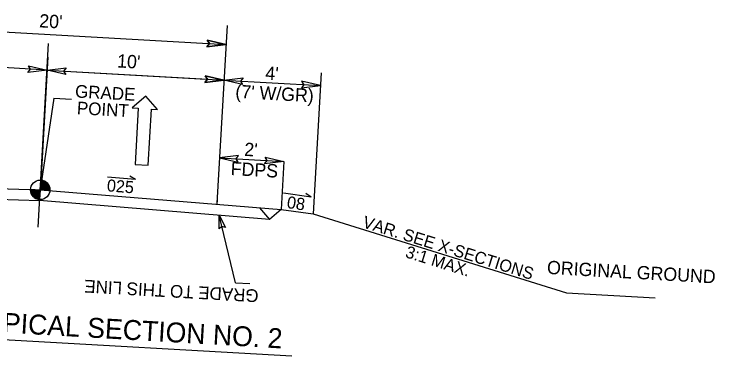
# Model space of a CAD drawing. Extents: x 2604316 to 2606605, y 617090 to 619543.
# Drawn here: x 2606244.6 to 2606592.8, y 617090 to 617260 of the extents above; entities that cross this region are included whole.
import ezdxf

# ---------------------------------------------------------------- set-up
doc = ezdxf.new("R2010")
doc.units = 0
for name, color, linetype in [('Pattern 1', 7, 'Continuous'), ('Prop Vertical Profile Curve Label', 7, 'Continuous'), ('Typical Grade Point Symbol CELL', 7, 'Continuous'), ('Typical Pavement Slope CELL', 7, 'Continuous'), ('Typical Pavement Slope Information CELL', 7, 'Continuous'), ('Typical Terminator CELL', 7, 'Continuous'), ('Typical Text Centerline CELL', 7, 'Continuous'), ('Typical Text General CELL', 7, 'Continuous')]:
    doc.layers.add(name, color=color, linetype=linetype)

msp = doc.modelspace()

# ---------------------------------------------------------------- linework, layer by layer
at = {"layer": 'Pattern 1'}
msp.add_line((2606519.08, 617121.38), (2606563.01, 617118.87), dxfattribs=at)
at = {"layer": 'Prop Vertical Profile Curve Label'}
for p, q in [((2606137.6, 617176.44), (2606257.57, 617172.61)), ((2606257.57, 617172.61), (2606377.21, 617162.79)), ((2606142.72, 617170.92), (2606257.27, 617167.27)), ((2606371.49, 617157.89), (2606257.27, 617167.27)), ((2606366.55, 617163.67), (2606371.49, 617157.89)), ((2606377.21, 617162.79), (2606371.49, 617157.89)), ((2606377.21, 617162.79), (2606393.11, 617160.6)), ((2606354.5, 617126.47), (2606346.51, 617159.95)), ((2606393.11, 617160.6), (2606519.08, 617121.38)), ((2606354.5, 617126.47), (2606361.62, 617126.07))]:
    msp.add_line(p, q, dxfattribs=at)
at = {"layer": 'Typical Grade Point Symbol CELL'}
for p, q in [((2606257.57, 617172.61), (2606257.85, 617177.44)), ((2606252.75, 617172.88), (2606257.57, 617172.61)), ((2606257.29, 617167.78), (2606257.57, 617172.61)), ((2606257.57, 617172.61), (2606257.29, 617167.78)), ((2606262.4, 617172.33), (2606257.57, 617172.61))]:
    msp.add_line(p, q, dxfattribs=at)
for points in [[(2606257.89, 617177.43), (2606257.89, 617177.43), (2606257.61, 617172.61)], [(2606257.99, 617177.43), (2606257.71, 617172.6)], [(2606258.08, 617177.41), (2606257.81, 617172.6)], [(2606258.18, 617177.41), (2606257.9, 617172.59)], [(2606258.27, 617177.39), (2606258, 617172.59)], [(2606258.37, 617177.37), (2606258.1, 617172.58)], [(2606258.47, 617177.36), (2606258.19, 617172.57)], [(2606258.56, 617177.34), (2606258.29, 617172.57)], [(2606258.66, 617177.33), (2606258.39, 617172.56)], [(2606258.75, 617177.3), (2606258.48, 617172.56)], [(2606258.85, 617177.27), (2606258.58, 617172.55)], [(2606258.94, 617177.24), (2606258.68, 617172.55)], [(2606259.04, 617177.22), (2606258.77, 617172.54)], [(2606259.13, 617177.18), (2606258.87, 617172.54)], [(2606259.23, 617177.15), (2606258.97, 617172.53)], [(2606259.32, 617177.11), (2606259.06, 617172.52)], [(2606259.42, 617177.08), (2606259.16, 617172.52)], [(2606259.51, 617177.04), (2606259.26, 617172.51)], [(2606259.61, 617176.99), (2606259.35, 617172.51)], [(2606259.7, 617176.94), (2606259.45, 617172.5)], [(2606259.8, 617176.89), (2606259.55, 617172.5)], [(2606259.89, 617176.85), (2606259.64, 617172.49)], [(2606259.98, 617176.8), (2606259.74, 617172.49)], [(2606260.08, 617176.74), (2606259.83, 617172.48)], [(2606260.17, 617176.68), (2606259.93, 617172.48)], [(2606260.26, 617176.62), (2606260.03, 617172.47)], [(2606260.36, 617176.56), (2606260.12, 617172.46)], [(2606260.45, 617176.49), (2606260.22, 617172.46)], [(2606260.54, 617176.42), (2606260.32, 617172.45)], [(2606260.64, 617176.34), (2606260.41, 617172.45)], [(2606260.73, 617176.27), (2606260.51, 617172.44)], [(2606260.82, 617176.19), (2606260.61, 617172.44)], [(2606260.91, 617176.1), (2606260.7, 617172.43)], [(2606261, 617176.01), (2606260.8, 617172.43)], [(2606261.1, 617175.92), (2606260.9, 617172.42)], [(2606252.77, 617172.88), (2606252.74, 617172.36)], [(2606252.86, 617172.88), (2606252.8, 617171.78)], [(2606252.96, 617172.87), (2606252.88, 617171.44)], [(2606253.06, 617172.87), (2606252.96, 617171.14)], [(2606253.15, 617172.86), (2606253.04, 617170.91)], [(2606253.25, 617172.86), (2606253.13, 617170.7)], [(2606253.35, 617172.85), (2606253.21, 617170.51)], [(2606253.44, 617172.84), (2606253.3, 617170.34)], [(2606253.54, 617172.84), (2606253.39, 617170.18)], [(2606253.64, 617172.83), (2606253.48, 617170.03)], [(2606253.73, 617172.83), (2606253.57, 617169.9)], [(2606253.83, 617172.82), (2606253.66, 617169.78)], [(2606253.93, 617172.82), (2606253.75, 617169.65)], [(2606254.02, 617172.81), (2606253.84, 617169.54)], [(2606254.12, 617172.81), (2606253.93, 617169.43)], [(2606254.21, 617172.8), (2606254.02, 617169.33)], [(2606254.31, 617172.8), (2606254.11, 617169.23)], [(2606254.41, 617172.79), (2606254.2, 617169.14)], [(2606254.5, 617172.78), (2606254.29, 617169.05)], [(2606254.6, 617172.78), (2606254.38, 617168.97)], [(2606254.7, 617172.77), (2606254.48, 617168.89)], [(2606254.79, 617172.77), (2606254.57, 617168.82)], [(2606254.89, 617172.76), (2606254.66, 617168.75)], [(2606254.99, 617172.76), (2606254.75, 617168.68)], [(2606255.08, 617172.75), (2606254.85, 617168.61)], [(2606255.18, 617172.75), (2606254.94, 617168.55)], [(2606255.28, 617172.74), (2606255.03, 617168.49)], [(2606255.37, 617172.73), (2606255.13, 617168.43)], [(2606255.47, 617172.73), (2606255.22, 617168.39)], [(2606255.57, 617172.72), (2606255.32, 617168.34)], [(2606255.66, 617172.72), (2606255.41, 617168.29)], [(2606255.76, 617172.71), (2606255.5, 617168.24)], [(2606255.86, 617172.71), (2606255.6, 617168.19)], [(2606255.95, 617172.7), (2606255.69, 617168.15)], [(2606256.05, 617172.7), (2606255.79, 617168.12)], [(2606256.15, 617172.69), (2606255.88, 617168.08)], [(2606256.24, 617172.69), (2606255.98, 617168.05)], [(2606256.34, 617172.68), (2606256.07, 617168.01)], [(2606256.44, 617172.67), (2606256.17, 617167.99)], [(2606256.53, 617172.67), (2606256.26, 617167.96)], [(2606256.63, 617172.66), (2606256.36, 617167.93)], [(2606256.72, 617172.66), (2606256.45, 617167.91)], [(2606256.82, 617172.65), (2606256.55, 617167.89)], [(2606256.92, 617172.65), (2606256.65, 617167.86)], [(2606257.01, 617172.64), (2606256.74, 617167.85)], [(2606257.11, 617172.64), (2606256.84, 617167.83)], [(2606257.21, 617172.63), (2606256.93, 617167.81)], [(2606257.3, 617172.62), (2606257.03, 617167.81)], [(2606257.4, 617172.62), (2606257.13, 617167.79)], [(2606257.5, 617172.61), (2606257.22, 617167.79), (2606257.22, 617167.79)], [(2606261.19, 617175.81), (2606260.99, 617172.41)], [(2606261.28, 617175.71), (2606261.09, 617172.41)], [(2606261.37, 617175.6), (2606261.19, 617172.4)], [(2606261.46, 617175.48), (2606261.28, 617172.4)], [(2606261.55, 617175.35), (2606261.38, 617172.39)], [(2606261.64, 617175.22), (2606261.48, 617172.39)], [(2606261.73, 617175.07), (2606261.57, 617172.38)], [(2606261.81, 617174.92), (2606261.67, 617172.38)], [(2606261.9, 617174.75), (2606261.76, 617172.37)], [(2606261.99, 617174.57), (2606261.86, 617172.37)], [(2606262.07, 617174.37), (2606261.96, 617172.36)], [(2606262.16, 617174.13), (2606262.05, 617172.35)], [(2606262.24, 617173.86), (2606262.15, 617172.35)], [(2606262.31, 617173.52), (2606262.25, 617172.34)], [(2606262.38, 617173.02), (2606262.34, 617172.34)]]:
    msp.add_lwpolyline(points, dxfattribs=at)
msp.add_circle((2606257.57, 617172.61), 4.83, dxfattribs=at)
for start, end in [(356.7307, 86.7307), (176.7307, 266.7307)]:
    msp.add_arc((2606257.57, 617172.61), 4.83, start, end, dxfattribs=at)
at = {"layer": 'Typical Pavement Slope CELL'}
for p, q in [((2606174.11, 617254.77), (2606349.82, 617244.76)), ((2606350.36, 617254.19), (2606345.34, 617166.01)), ((2606350.36, 617254.19), (2606345.34, 617166.01)), ((2606260.96, 617232.1), (2606173.1, 617237.1)), ((2606261.32, 617238.49), (2606257.64, 617173.76)), ((2606260.96, 617232.1), (2606340.83, 617227.55)), ((2606260.96, 617232.1), (2606348.82, 617227.09)), ((2606397.1, 617230.75), (2606393.11, 617160.6)), ((2606348.82, 617227.09), (2606396.74, 617224.36)), ((2606264.33, 617218.14), (2606257.57, 617172.61)), ((2606264.33, 617218.14), (2606273.12, 617217.64)), ((2606310, 617219.21), (2606303.25, 617213.28)), ((2606315.83, 617212.57), (2606310, 617219.21)), ((2606303.25, 617213.28), (2606306.25, 617213.11)), ((2606306.25, 617213.11), (2606304.66, 617185.16)), ((2606311.25, 617184.78), (2606312.84, 617212.74)), ((2606312.84, 617212.74), (2606315.83, 617212.57)), ((2606346.62, 617188.53), (2606378.57, 617186.71)), ((2606378.57, 617186.71), (2606377.21, 617162.79)), ((2606304.66, 617185.16), (2606311.25, 617184.78)), ((2606302.16, 617179.56), (2606304.95, 617177.98)), ((2606290.99, 617179.06), (2606304.95, 617177.98)), ((2606378.37, 617171.04), (2606392.24, 617169.13)), ((2606389.55, 617170.87), (2606392.24, 617169.13)), ((2606345.43, 617167.61), (2606345.3, 617165.41)), ((2606142.71, 617103.71), (2606382.64, 617090.04))]:
    msp.add_line(p, q, dxfattribs=at)
at = {"layer": 'Typical Terminator CELL'}
for points in [[(2606340.56, 617246.91), (2606349.82, 617244.76), (2606340.32, 617243.64), (2606341.61, 617245.23)], [(2606340.37, 617243.68), (2606349.82, 617244.76), (2606340.51, 617246.96), (2606341.61, 617245.23)], [(2606251.69, 617234.24), (2606260.96, 617232.1), (2606251.45, 617230.97), (2606252.75, 617232.56)], [(2606270.23, 617229.95), (2606260.96, 617232.1), (2606270.46, 617233.22), (2606269.17, 617231.63)], [(2606339.55, 617229.24), (2606348.82, 617227.09), (2606339.31, 617225.96), (2606340.6, 617227.56)], [(2606339.37, 617226.01), (2606348.82, 617227.09), (2606339.5, 617229.29), (2606340.6, 617227.56)], [(2606358.08, 617224.95), (2606348.82, 617227.09), (2606358.32, 617228.22), (2606357.03, 617226.62)], [(2606387.29, 617223.28), (2606396.74, 617224.36), (2606387.42, 617226.56), (2606388.53, 617224.83)], [(2606356.07, 617189.61), (2606346.62, 617188.53), (2606355.94, 617186.33), (2606354.84, 617188.06)], [(2606369.3, 617188.86), (2606378.57, 617186.71), (2606369.06, 617185.58), (2606370.35, 617187.18)], [(2606346.46, 617153.19), (2606346.51, 617159.95), (2606349.67, 617153.92), (2606347.85, 617154.35)]]:
    msp.add_lwpolyline(points, close=True, dxfattribs=at)
at = {"layer": 'Typical Text Centerline CELL'}
msp.add_line((2606256.52, 617154.06), (2606261.71, 617245.3), dxfattribs=at)

# ---------------------------------------------------------------- texts
at = {"layer": 'Typical Pavement Slope CELL'}
for s, height, rotation, p in [("20'", 6.6, 356.7403, (2606256.93, 617253.37)), ("10'", 6.6, 356.7403, (2606295.62, 617233.43)), ("4'", 6.6, 356.7403, (2606369.23, 617227.36)), ("(7' W/GR)", 6.6, 356.7403, (2606354.38, 617218.29)), ("2'", 6.6, 356.7403, (2606358.8, 617189.49)), ('FDPS', 6.6, 356.7403, (2606352.04, 617179.96)), ('VAR. SEE X-SECTIONS', 6, 342.704, (2606417.27, 617154.06)), ('3:1 MAX.', 6, 342.704, (2606438.53, 617139.2)), ('ROADWAY TYPICAL SECTION NO. 2', 9.9, 356.7403, (2606149.96, 617106.74))]:
    msp.add_text(s, height=height, rotation=rotation, dxfattribs=at).set_placement(p)
at = {"layer": 'Typical Pavement Slope Information CELL'}
for s, rotation, p in [('025', 355.5945, (2606290.53, 617171.87)), ('08', 352.1663, (2606379.84, 617163.57))]:
    msp.add_text(s, height=6, rotation=rotation, dxfattribs=at).set_placement(p)
at = {"layer": 'Typical Text General CELL'}
for s, height, rotation, p in [('GRADE', 6.302, 356.7403, (2606274.76, 617218.52)), ('POINT', 6.302, 356.7403, (2606275.66, 617210.2)), ('ORIGINAL GROUND', 6.6, 356.7403, (2606509.18, 617130.86)), ('GRADE TO THIS LINE', 6.302, 176.7403, (2606366.18, 617122.99))]:
    msp.add_text(s, height=height, rotation=rotation, dxfattribs=at).set_placement(p)

doc.saveas('drawing.dxf')
